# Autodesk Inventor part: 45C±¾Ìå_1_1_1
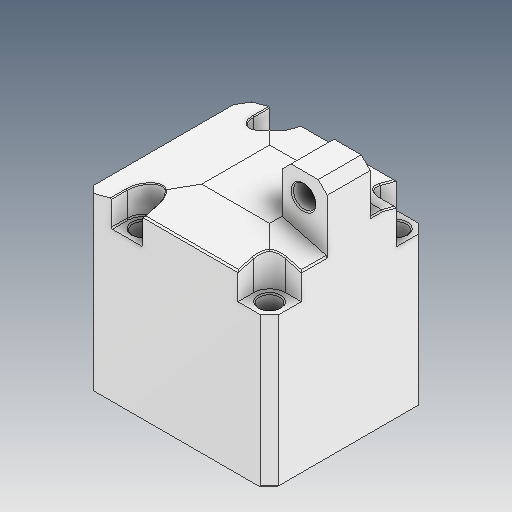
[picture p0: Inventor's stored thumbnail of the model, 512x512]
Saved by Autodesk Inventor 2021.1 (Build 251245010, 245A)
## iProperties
Created: 2021-05
Part Number: 45C±¾Ìå_1_1_1
Material: Ogólny
Document SubType Name: Modeling
Designer: user
Density: 1 g/cm^3
Appearance: Domyślna
Author: user
Revision Number: ÈÎºÎ
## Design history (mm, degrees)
feature "ÊäÈë1"
node "Bryła1"
